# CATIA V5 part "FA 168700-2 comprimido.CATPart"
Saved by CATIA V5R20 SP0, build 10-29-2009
Part number: FA 168700-2 comprimido
Revision: ANY
Definition: UNKNOWN
Nomenclature: FA 168700-2 comprimido
Source: Unknown
Bounding box of the stored display mesh (mm): x -2.8 to 2.8, y 0 to 4.04, z -2.8 to 2.8
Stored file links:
  C:\Users\Utente\Desktop\IO LAVORO\3D X SITO CF\CUMSA\3D files FA\FA 1687SF\FA 168700-2 comprimido.CATPart

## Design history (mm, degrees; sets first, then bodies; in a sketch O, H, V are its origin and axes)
Body1 "Cortar-Extruir1" (main body)
  Solid1: solid without history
